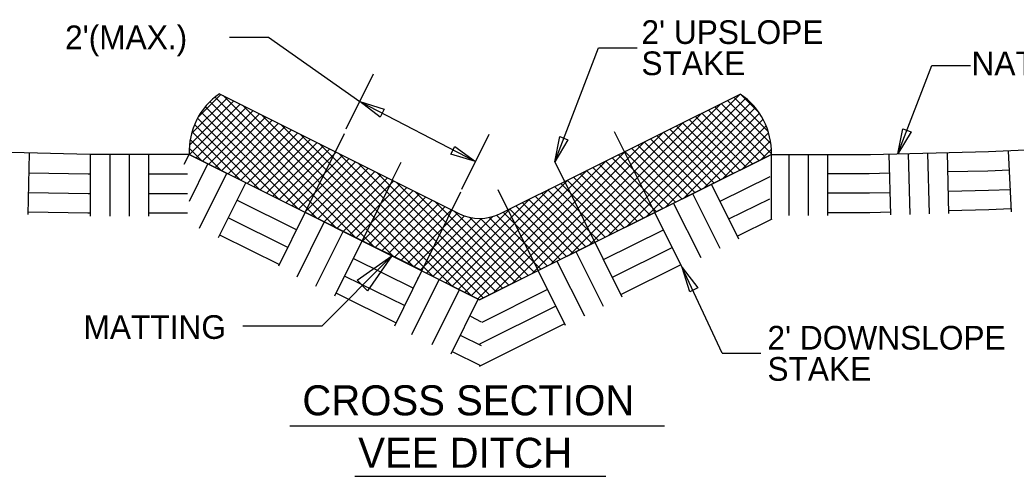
# Model space of a CAD drawing. Extents: x 8096 to 9796, y 9620 to 10720.
# Drawn here: x 8436.8 to 8876.7, y 9923.8 to 10125.2 of the extents above; entities that cross this region are included whole.
import ezdxf

# ---------------------------------------------------------------- set-up
doc = ezdxf.new("R2010")
doc.units = 0
for name, color, linetype in [('Default', 7, 'Continuous'), ('Old_Level_1', 7, 'Continuous'), ('Old_Level_2', 7, 'Continuous'), ('Old_Level_20', 7, 'Continuous')]:
    doc.layers.add(name, color=color, linetype=linetype)

msp = doc.modelspace()

# ---------------------------------------------------------------- linework, layer by layer
at = {"layer": 'Default'}
for p, q in [((8515.41, 10082.15), (8525.57, 10092.31)), ((8524.94, 10092.62), (8630.85, 10039.67)), ((8526.54, 10091.82), (8593.58, 10024.78)), ((8648.7, 10039.65), (8754.87, 10092.47)), ((8688.13, 10025.76), (8754.81, 10092.44)), ((8755.32, 10092.15), (8763.12, 10084.34)), ((8511.65, 10069.89), (8531.23, 10089.48)), ((8511.73, 10065.74), (8534.06, 10088.06)), ((8512.55, 10075.04), (8528.4, 10090.89)), ((8520.74, 10089.13), (8576.6, 10033.28)), ((8522.99, 10091.13), (8585.09, 10029.03)), ((8535.03, 10087.58), (8602.07, 10020.53)), ((8679.68, 10021.55), (8746.37, 10088.24)), ((8696.57, 10029.96), (8757.29, 10090.68)), ((8705.01, 10034.16), (8759.51, 10088.66)), ((8746.45, 10088.28), (8768.62, 10066.12)), ((8749.29, 10089.69), (8768.37, 10070.61)), ((8752.12, 10091.1), (8767.19, 10076.03)), ((8514.56, 10064.32), (8536.89, 10086.65)), ((8516.88, 10084.51), (8559.61, 10041.78)), ((8517.39, 10062.91), (8539.71, 10085.23)), ((8518.71, 10086.93), (8568.1, 10037.53)), ((8520.22, 10061.49), (8542.54, 10083.82)), ((8543.51, 10083.34), (8610.57, 10016.28)), ((8671.24, 10017.35), (8737.92, 10084.04)), ((8713.46, 10038.36), (8761.53, 10086.44)), ((8721.9, 10042.56), (8763.35, 10084.01)), ((8737.95, 10084.05), (8760.33, 10061.68)), ((8740.79, 10085.46), (8763.16, 10063.09)), ((8743.62, 10086.87), (8766, 10064.5)), ((8513.88, 10079.02), (8542.62, 10050.28)), ((8515.26, 10081.89), (8551.12, 10046.03)), ((8523.05, 10060.08), (8545.37, 10082.41)), ((8525.87, 10058.66), (8548.2, 10080.99)), ((8528.7, 10057.25), (8551.03, 10079.58)), ((8552, 10079.09), (8619.06, 10012.03)), ((8662.79, 10013.15), (8729.48, 10079.84)), ((8729.45, 10079.83), (8751.83, 10057.45)), ((8730.34, 10046.76), (8764.94, 10081.36)), ((8732.29, 10081.23), (8754.66, 10058.86)), ((8735.12, 10082.64), (8757.5, 10060.27)), ((8512.78, 10075.88), (8534.13, 10054.53)), ((8531.53, 10055.83), (8553.86, 10078.16)), ((8534.36, 10054.42), (8556.68, 10076.75)), ((8537.18, 10053), (8559.51, 10075.33)), ((8560.48, 10074.85), (8627.55, 10007.78)), ((8654.35, 10008.95), (8721.04, 10075.64)), ((8718.12, 10074.19), (8740.5, 10051.81)), ((8720.96, 10075.6), (8743.33, 10053.22)), ((8723.79, 10077.01), (8746.16, 10054.63)), ((8726.62, 10078.42), (8749, 10056.04)), ((8738.79, 10050.96), (8766.31, 10078.48)), ((8747.23, 10055.16), (8767.42, 10075.35)), ((8511.98, 10072.44), (8525.64, 10058.78)), ((8540.01, 10051.59), (8562.34, 10073.92)), ((8542.84, 10050.17), (8565.17, 10072.51)), ((8545.67, 10048.76), (8568, 10071.09)), ((8568.97, 10070.61), (8636.04, 10003.53)), ((8645.91, 10004.75), (8712.59, 10071.44)), ((8709.62, 10069.96), (8732, 10047.58)), ((8712.46, 10071.37), (8734.83, 10048.99)), ((8715.29, 10072.78), (8737.66, 10050.4)), ((8755.67, 10059.36), (8768.19, 10071.88)), ((8511.53, 10068.64), (8517.15, 10063.03)), ((8548.49, 10047.34), (8570.83, 10069.68)), ((8551.32, 10045.93), (8573.66, 10068.26)), ((8554.15, 10044.51), (8576.48, 10066.85)), ((8556.98, 10043.1), (8579.31, 10065.44)), ((8577.45, 10066.37), (8641.34, 10002.48)), ((8638.98, 10002.06), (8704.15, 10067.24)), ((8701.12, 10065.73), (8723.5, 10043.35)), ((8703.96, 10067.14), (8726.33, 10044.76)), ((8706.79, 10068.55), (8729.16, 10046.17)), ((8764.12, 10063.56), (8768.58, 10068.03)), ((8559.8, 10041.68), (8582.14, 10064.02)), ((8562.63, 10040.27), (8584.97, 10062.61)), ((8565.46, 10038.85), (8587.8, 10061.19)), ((8585.94, 10062.12), (8644.17, 10003.89)), ((8636.15, 10003.48), (8695.71, 10063.03)), ((8692.62, 10061.5), (8715, 10039.13)), ((8695.46, 10062.91), (8717.83, 10040.54)), ((8698.29, 10064.32), (8720.67, 10041.95)), ((8760.33, 10061.68), (8760.33, 10061.68)), ((8760.33, 10061.68), (8760.33, 10061.68)), ((8763.16, 10063.09), (8763.16, 10063.09)), ((8763.16, 10063.09), (8763.16, 10063.09)), ((8764.12, 10063.56), (8764.12, 10063.56)), ((8764.12, 10063.56), (8764.12, 10063.56)), ((8766, 10064.5), (8766, 10064.5)), ((8766, 10064.5), (8766, 10064.5)), ((8568.29, 10037.44), (8590.63, 10059.78)), ((8571.11, 10036.02), (8593.45, 10058.36)), ((8573.94, 10034.61), (8596.28, 10056.95)), ((8594.42, 10057.88), (8647.01, 10005.3)), ((8633.32, 10004.89), (8687.26, 10058.83)), ((8684.12, 10057.27), (8706.5, 10034.9)), ((8686.96, 10058.68), (8709.33, 10036.31)), ((8689.79, 10060.09), (8712.17, 10037.72)), ((8751.83, 10057.45), (8751.83, 10057.45)), ((8751.83, 10057.45), (8751.83, 10057.45)), ((8754.66, 10058.86), (8754.66, 10058.86)), ((8754.66, 10058.86), (8754.66, 10058.86)), ((8755.67, 10059.36), (8755.67, 10059.36)), ((8755.67, 10059.36), (8755.67, 10059.36)), ((8757.5, 10060.27), (8757.5, 10060.27)), ((8757.5, 10060.27), (8757.5, 10060.27)), ((8576.77, 10033.19), (8599.11, 10055.54)), ((8579.6, 10031.78), (8601.94, 10054.12)), ((8582.42, 10030.36), (8604.77, 10052.71)), ((8602.91, 10053.64), (8649.84, 10006.71)), ((8630.49, 10006.31), (8678.82, 10054.63)), ((8675.63, 10053.04), (8698, 10030.67)), ((8678.46, 10054.45), (8700.83, 10032.08)), ((8681.29, 10055.86), (8703.67, 10033.49)), ((8743.33, 10053.22), (8743.33, 10053.22)), ((8743.33, 10053.22), (8743.33, 10053.22)), ((8746.16, 10054.63), (8746.16, 10054.63)), ((8746.16, 10054.63), (8746.16, 10054.63)), ((8747.23, 10055.16), (8747.23, 10055.16)), ((8749, 10056.04), (8749, 10056.04)), ((8749, 10056.04), (8749, 10056.04)), ((8585.25, 10028.95), (8607.6, 10051.29)), ((8588.08, 10027.53), (8610.43, 10049.88)), ((8590.91, 10026.12), (8613.25, 10048.46)), ((8611.39, 10049.39), (8652.67, 10008.12)), ((8627.67, 10007.72), (8670.38, 10050.43)), ((8667.13, 10048.82), (8689.5, 10026.44)), ((8669.96, 10050.23), (8692.33, 10027.85)), ((8672.79, 10051.63), (8695.17, 10029.26)), ((8734.83, 10048.99), (8734.83, 10048.99)), ((8734.83, 10048.99), (8734.83, 10048.99)), ((8737.66, 10050.4), (8737.66, 10050.4)), ((8738.79, 10050.96), (8738.79, 10050.96)), ((8738.79, 10050.96), (8738.79, 10050.96)), ((8740.5, 10051.81), (8740.5, 10051.81)), ((8740.5, 10051.81), (8740.5, 10051.81)), ((8593.73, 10024.7), (8616.08, 10047.05)), ((8596.56, 10023.29), (8618.91, 10045.64)), ((8599.39, 10021.87), (8621.74, 10044.22)), ((8619.88, 10045.15), (8655.5, 10009.53)), ((8624.84, 10009.14), (8661.93, 10046.23)), ((8658.63, 10044.59), (8681, 10022.21)), ((8661.46, 10046), (8683.84, 10023.62)), ((8664.29, 10047.41), (8686.67, 10025.03)), ((8726.33, 10044.76), (8726.33, 10044.76)), ((8729.16, 10046.17), (8729.16, 10046.17)), ((8729.16, 10046.17), (8729.17, 10046.17)), ((8730.34, 10046.76), (8730.34, 10046.76)), ((8730.34, 10046.76), (8730.34, 10046.76)), ((8732, 10047.58), (8732, 10047.58)), ((8732, 10047.58), (8732, 10047.58)), ((8602.22, 10020.46), (8624.57, 10042.81)), ((8605.05, 10019.04), (8627.4, 10041.39)), ((8607.87, 10017.63), (8630.22, 10039.98)), ((8622.01, 10010.55), (8653.49, 10042.03)), ((8628.36, 10040.91), (8658.34, 10010.94)), ((8647.23, 10039.02), (8669.67, 10016.57)), ((8650.13, 10040.36), (8672.5, 10017.98)), ((8652.96, 10041.77), (8675.34, 10019.39)), ((8655.79, 10043.18), (8678.17, 10020.8)), ((8715, 10039.13), (8715, 10039.13)), ((8715, 10039.13), (8715, 10039.13)), ((8717.83, 10040.54), (8717.83, 10040.54)), ((8720.67, 10041.95), (8720.67, 10041.94)), ((8721.9, 10042.56), (8721.9, 10042.56)), ((8723.5, 10043.35), (8723.5, 10043.35)), ((8723.5, 10043.35), (8723.5, 10043.35)), ((8610.7, 10016.21), (8633.18, 10038.7)), ((8613.53, 10014.8), (8636.57, 10037.84)), ((8616.36, 10013.38), (8640.57, 10037.6)), ((8619.18, 10011.97), (8645.66, 10038.44)), ((8635.46, 10038.05), (8661.17, 10012.34)), ((8640.17, 10037.59), (8664, 10013.75)), ((8643.98, 10038.02), (8666.84, 10015.16)), ((8706.5, 10034.9), (8706.5, 10034.9)), ((8706.5, 10034.9), (8706.5, 10034.9)), ((8709.33, 10036.31), (8709.33, 10036.31)), ((8709.33, 10036.31), (8709.33, 10036.31)), ((8712.17, 10037.72), (8712.17, 10037.72)), ((8712.17, 10037.72), (8712.17, 10037.72)), ((8713.45, 10038.36), (8713.46, 10038.36)), ((8713.46, 10038.36), (8713.46, 10038.36)), ((8698, 10030.67), (8698, 10030.67)), ((8698, 10030.67), (8698, 10030.67)), ((8700.83, 10032.08), (8700.83, 10032.08)), ((8700.83, 10032.08), (8700.83, 10032.08)), ((8703.67, 10033.49), (8703.67, 10033.49)), ((8703.67, 10033.49), (8703.67, 10033.49)), ((8705.01, 10034.16), (8705.01, 10034.16)), ((8705.01, 10034.16), (8705.01, 10034.16)), ((8689.5, 10026.44), (8689.5, 10026.44)), ((8689.5, 10026.44), (8689.5, 10026.44)), ((8692.33, 10027.85), (8692.33, 10027.85)), ((8692.33, 10027.85), (8692.33, 10027.85)), ((8695.17, 10029.26), (8695.17, 10029.26)), ((8695.17, 10029.26), (8695.17, 10029.26)), ((8696.57, 10029.96), (8696.57, 10029.96)), ((8696.57, 10029.96), (8696.57, 10029.96)), ((8679.68, 10021.55), (8679.68, 10021.55)), ((8681, 10022.21), (8681, 10022.21)), ((8681, 10022.21), (8681, 10022.21)), ((8683.84, 10023.62), (8683.84, 10023.62)), ((8683.84, 10023.62), (8683.84, 10023.62)), ((8686.67, 10025.03), (8686.67, 10025.03)), ((8686.67, 10025.03), (8686.67, 10025.03)), ((8688.12, 10025.75), (8688.13, 10025.76)), ((8688.13, 10025.76), (8688.13, 10025.76)), ((8671.24, 10017.35), (8671.24, 10017.35)), ((8671.24, 10017.35), (8671.24, 10017.35)), ((8672.5, 10017.98), (8672.5, 10017.98)), ((8672.5, 10017.98), (8672.5, 10017.98)), ((8675.34, 10019.39), (8675.34, 10019.39)), ((8675.34, 10019.39), (8675.34, 10019.39)), ((8678.17, 10020.8), (8678.17, 10020.8)), ((8678.17, 10020.8), (8678.17, 10020.8)), ((8662.79, 10013.15), (8662.79, 10013.15)), ((8662.79, 10013.15), (8662.79, 10013.15)), ((8664, 10013.75), (8664, 10013.75)), ((8664, 10013.75), (8664, 10013.75)), ((8666.84, 10015.16), (8666.84, 10015.16)), ((8666.84, 10015.16), (8666.84, 10015.16)), ((8669.67, 10016.57), (8669.67, 10016.57)), ((8669.67, 10016.57), (8669.67, 10016.57)), ((8654.35, 10008.95), (8654.35, 10008.95)), ((8654.35, 10008.95), (8654.35, 10008.95)), ((8655.5, 10009.53), (8655.5, 10009.53)), ((8655.5, 10009.53), (8655.5, 10009.53)), ((8658.34, 10010.94), (8658.34, 10010.94)), ((8658.34, 10010.94), (8658.34, 10010.94)), ((8661.17, 10012.34), (8661.17, 10012.34)), ((8661.17, 10012.34), (8661.17, 10012.34)), ((8644.17, 10003.89), (8644.17, 10003.89)), ((8644.17, 10003.89), (8644.17, 10003.89)), ((8645.91, 10004.75), (8645.91, 10004.75)), ((8645.91, 10004.75), (8645.91, 10004.75)), ((8647.01, 10005.3), (8647.01, 10005.3)), ((8647.01, 10005.3), (8647.01, 10005.3)), ((8649.84, 10006.71), (8649.84, 10006.71)), ((8649.84, 10006.71), (8649.84, 10006.71)), ((8652.67, 10008.12), (8652.67, 10008.12)), ((8652.67, 10008.12), (8652.67, 10008.12)), ((8641.34, 10002.48), (8641.34, 10002.48)), ((8641.34, 10002.48), (8641.34, 10002.48))]:
    msp.add_line(p, q, dxfattribs=at)
for points in [[(8767.29, 10065.14), (8639.74, 10001.68), (8511.52, 10065.85)], [(8768.62, 10065.8), (8639.74, 10001.68)], [(8587.92, 10027.62), (8639.74, 10001.68), (8690.98, 10027.18)]]:
    msp.add_lwpolyline(points, dxfattribs=at)
for centre, radius, start, end in [((8542.38, 10067.13), 30.88, 124.3738, 182.3853), ((8737.79, 10066.79), 30.85, 358.1641, 56.3637), ((8639.79, 10057.56), 20, 243.4349, 296.4513)]:
    msp.add_arc(centre, radius, start, end, dxfattribs=at)
at = {"layer": 'Old_Level_1'}
for p, q in [((8529.37, 10117.55), (8546.5, 10117.55)), ((8673.01, 10062.63), (8692.28, 10112.94)), ((8692.28, 10112.94), (8709.41, 10112.94)), ((8824.53, 10066.1), (8839.46, 10105.07)), ((8839.46, 10105.07), (8856.59, 10105.07)), ((8580.85, 10077.13), (8592.88, 10101.41)), ((8562.81, 10040.18), (8580.08, 10075.06)), ((8631.98, 10050.55), (8644, 10074.83)), ((8717.13, 10040.19), (8699.39, 10075.84)), ((8440.41, 10039.32), (8441.05, 10066.45)), ((8468, 10038.62), (8468, 10065.8)), ((8476.59, 10038.62), (8476.59, 10065.8)), ((8485.13, 10038.62), (8485.13, 10065.8)), ((8493.67, 10038.62), (8493.67, 10065.8)), ((8509.35, 10061.56), (8511.5, 10065.8)), ((8768.62, 10037.18), (8768.62, 10065.8)), ((8776.46, 10038.91), (8776.46, 10065.8)), ((8785.05, 10038.91), (8785.05, 10065.8)), ((8793.59, 10038.91), (8793.59, 10065.8)), ((8821.35, 10039.2), (8820.66, 10066.01)), ((8829.95, 10039.32), (8829.26, 10066.22)), ((8838.43, 10039.61), (8837.79, 10066.42)), ((8847.03, 10039.78), (8846.39, 10066.63)), ((8874.61, 10040.54), (8873.4, 10067.48)), ((8511.61, 10045.24), (8519.78, 10061.68)), ((8601.24, 10054.47), (8605.21, 10062.47)), ((8677.35, 10053.9), (8673.01, 10062.63)), ((8516.03, 10033.33), (8528.22, 10057.55)), ((8524.45, 10029.15), (8536.56, 10053.32)), ((8575.91, 10003.42), (8601.39, 10054.75)), ((8702.81, 10002.84), (8677.35, 10053.9)), ((8754.21, 10028.46), (8742.22, 10052.67)), ((8614.23, 10014.43), (8631.49, 10049.27)), ((8665.64, 10014.57), (8647.94, 10050.15)), ((8745.97, 10024.33), (8733.89, 10048.49)), ((8737.66, 10020.15), (8725.46, 10044.31)), ((8551.17, 10016.68), (8562.81, 10040.18)), ((8729.24, 10015.91), (8717.16, 10040.19)), ((8559.18, 10011.73), (8571.19, 10035.98)), ((8567.43, 10007.61), (8579.6, 10031.78)), ((8694.51, 9998.66), (8682.43, 10022.76)), ((8686.2, 9994.48), (8674, 10018.58)), ((8602.28, 9990.18), (8614.3, 10014.46)), ((8677.72, 9990.29), (8665.64, 10014.57)), ((8746.84, 9978.07), (8729.24, 10015.91)), ((8609.88, 9986.29), (8621.97, 10010.57)), ((8618.89, 9981.93), (8630.97, 10006.15)), ((8627.19, 9977.75), (8639.22, 10001.97)), ((8746.84, 9978.07), (8763.98, 9978.07))]:
    msp.add_line(p, q, dxfattribs=at)
for points in [[(8586.86, 10089.27), (8637.99, 10062.69)], [(8511.5, 10065.8), (8467.7, 10065.8), (8415.43, 10067.08), (8362.65, 10069.49)], [(8511.5, 10065.8), (8614.07, 10014.75)], [(8768.62, 10065.8), (8812.35, 10065.8), (8864.57, 10067.08), (8916.78, 10069.46)], [(8440.93, 10057.67), (8466.89, 10057.21), (8468, 10057.21)], [(8493.67, 10057.21), (8510.8, 10057.21)], [(8793.59, 10057.38), (8811.83, 10057.38), (8820.95, 10057.67)], [(8846.5, 10058.25), (8864.16, 10058.66), (8873.86, 10059.01)], [(8745.97, 10045.13), (8768.15, 10056.04)], [(8440.7, 10049.07), (8466.89, 10048.61), (8468, 10048.61)], [(8493.67, 10048.61), (8510.8, 10048.61)], [(8793.59, 10048.84), (8811.94, 10048.84), (8821.24, 10049.07)], [(8846.79, 10049.66), (8864.45, 10050.06), (8874.09, 10050.41)], [(8532.75, 10045.59), (8559.05, 10032.59)], [(8749.86, 10037.34), (8767.92, 10046.29)], [(8440.52, 10040.54), (8466.72, 10040.01), (8468, 10040.01)], [(8493.67, 10040.01), (8510.8, 10040.01)], [(8793.59, 10040.25), (8812.06, 10040.25), (8821.47, 10040.54)], [(8846.91, 10041.06), (8864.68, 10041.52), (8874.44, 10041.93)], [(8528.92, 10037.87), (8555.2, 10024.81)], [(8753.52, 10029.73), (8768.97, 10037.34)], [(8525.15, 10030.2), (8551.42, 10017.18)], [(8694.51, 10019.4), (8720.93, 10032.52)], [(8698.4, 10011.61), (8724.77, 10024.8)], [(8584.16, 10019.92), (8610.58, 10006.79)], [(8702.17, 10004), (8728.54, 10017.13)], [(8580.26, 10012.14), (8606.69, 9999.07)], [(8612.67, 10011.26), (8612.56, 10011.26), (8612.5, 10011.32)], [(8576.6, 10004.59), (8602.92, 9991.4)], [(8640.84, 9991.81), (8669.65, 10006.15)], [(8639.85, 9982.17), (8673.25, 9998.78)], [(8635.73, 9994.36), (8640.43, 9991.92)], [(8639.74, 9972.35), (8677.08, 9990.99)], [(8631.55, 9985.88), (8640.43, 9981.47)], [(8627.95, 9978.68), (8639.85, 9972.76)]]:
    msp.add_lwpolyline(points, dxfattribs=at)
at = {"layer": 'Old_Level_2'}
msp.add_line((8546.5, 10117.55), (8586.86, 10089.27), dxfattribs=at)
for points in [[(8586.86, 10089.27), (8597.64, 10085.79), (8595.81, 10082.35)], [(8824.53, 10066.1), (8826.74, 10077.19), (8830.34, 10075.8)], [(8673.01, 10062.63), (8675.21, 10073.72), (8678.81, 10072.33)], [(8637.99, 10062.69), (8627.14, 10065.94), (8628.89, 10069.41)], [(8601.05, 10021.05), (8590.24, 10005.6), (8585.66, 10010.24)], [(8729.24, 10015.91), (8736.09, 10006.91), (8732.67, 10005.14)]]:
    msp.add_lwpolyline(points, close=True, dxfattribs=at)
msp.add_lwpolyline([(8601.05, 10021.05), (8570.09, 9990.03), (8535.24, 9990.03)], dxfattribs=at)
at = {"layer": 'Old_Level_20'}
for p, q in [((8556.04, 9945.92), (8721.4, 9945.92)), ((8584.68, 9923.8), (8695.55, 9923.8))]:
    msp.add_line(p, q, dxfattribs=at)

# ---------------------------------------------------------------- texts
at = {"layer": 'Old_Level_1'}
for s, height, p in [("2'(MAX.)", 10.454, (8456.71, 10112.32)), ("2' UPSLOPE", 10.454, (8711.25, 10114.63)), ('STAKE', 10.454, (8711.25, 10100.86)), ('NATURAL GROUND', 10.4544, (8857.01, 10100.82)), ("2' DOWNSLOPE", 10.4544, (8766.89, 9979.66)), ('STAKE', 10.454, (8766.89, 9965.89)), ('CROSS SECTION', 13.2422, (8561.5, 9950.63)), ('VEE DITCH', 13.242, (8586.19, 9927.46))]:
    msp.add_text(s, height=height, dxfattribs=at).set_placement(p)
at = {"layer": 'Old_Level_2'}
msp.add_text('MATTING', height=10.454, dxfattribs=at).set_placement((8464.86, 9984.38))

doc.saveas('drawing.dxf')
